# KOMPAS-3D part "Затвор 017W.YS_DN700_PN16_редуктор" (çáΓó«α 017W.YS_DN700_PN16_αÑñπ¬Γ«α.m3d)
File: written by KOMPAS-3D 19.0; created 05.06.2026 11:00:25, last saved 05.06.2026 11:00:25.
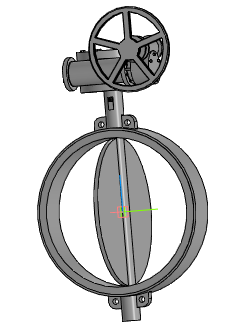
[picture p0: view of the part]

Document properties: Автор: Энергия; Полное имя файла: ..\..\..\3d для проектировщиков\x.x Тип 017W.Y(S) Затвор дисковый поворотный межфланцевый\Затвор 017W.Y(S)_DN50-DN1200_редуктор\Затвор 017W.YS_DN700_PN16_редуктор.a3d

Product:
- Part/product: Затвор 017W.YS_DN700_PN16_редуктор
    Масса: 393.264

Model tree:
1. Операция без истории:1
